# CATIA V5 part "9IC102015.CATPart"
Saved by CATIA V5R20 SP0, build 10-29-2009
Part number: 9IC102015
Revision: ANY
Definition: UNKNOWN
Nomenclature: 9IC102015
Source: Unknown
Bounding box of the stored display mesh (mm): x -5 to 5, y -5 to 5, z 0 to 20
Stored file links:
  C:\Users\Utente\Desktop\IO LAVORO\3D X SITO CF\CUMSA\3D files CC\CCHS5328\9IC102015.CATPart
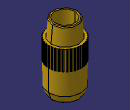
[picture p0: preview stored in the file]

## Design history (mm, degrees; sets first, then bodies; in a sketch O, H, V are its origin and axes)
Body1 "MatrizC1" (main body)
  Solid1: solid without history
